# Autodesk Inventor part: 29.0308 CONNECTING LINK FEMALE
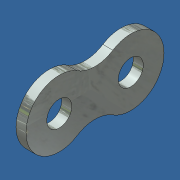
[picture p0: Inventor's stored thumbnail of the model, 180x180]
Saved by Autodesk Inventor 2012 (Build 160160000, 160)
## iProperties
Created: 2013-10
Part Number: 29.0308 CONNECTING LINK FEMALE
Material: Steel
Document SubType Name: Modeling
Designer: Admin
Density: 7.85 g/cm^3
Mass: 2.855 g
Surface Area: 5.72886 cm^2
Volume: 0.363694 cm^3
Author: Admin
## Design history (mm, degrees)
node "Product1"
node "Base1"
body "Solid1"
